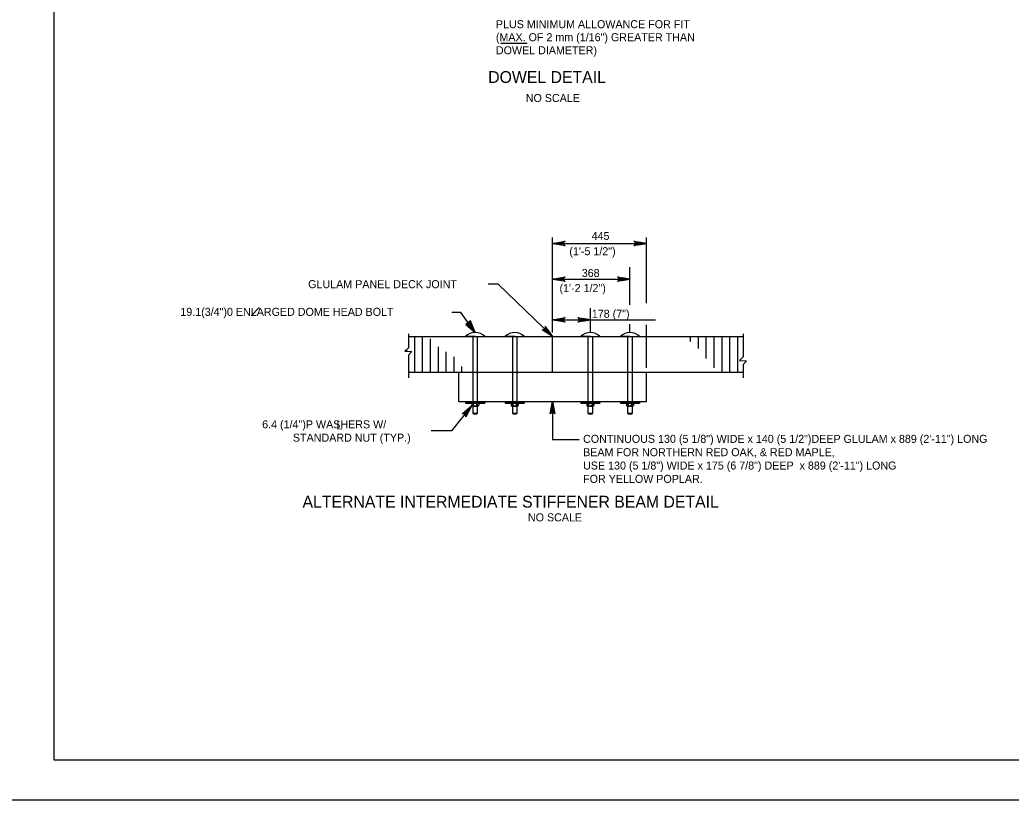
# Model space of a CAD drawing. Extents: x 638263 to 640360, y 293683 to 298655.
# Drawn here: x 639303.6 to 639675, y 294277.5 to 294570 of the extents above; entities that cross this region are included whole.
import ezdxf

# ---------------------------------------------------------------- set-up
doc = ezdxf.new("R2010")
doc.units = 0
for name, color, linetype in [('2', 7, 'Continuous'), ('3', 7, 'Continuous'), ('5', 7, 'Continuous'), ('PLT-BNDY', 7, 'Continuous')]:
    doc.layers.add(name, color=color, linetype=linetype)

msp = doc.modelspace()

# ---------------------------------------------------------------- linework, layer by layer
at = {"layer": '2'}
for p, q in [((639316.46, 294292.46), (639316.46, 294856.46)), ((639449.25, 294452.3), (639449.25, 294447.04)), ((639449.25, 294451.21), (639574.61, 294451.21)), ((639474.18, 294451.21), (639470.61, 294451.21)), ((639473.39, 294422.39), (639473.39, 294451.21)), ((639474.18, 294451.21), (639477.75, 294451.21)), ((639474.97, 294451.21), (639474.97, 294422.39)), ((639488.23, 294422.39), (639488.23, 294451.21)), ((639489.8, 294451.21), (639489.8, 294422.39)), ((639503.18, 294437.92), (639503.18, 294451.21)), ((639516.56, 294422.39), (639516.56, 294451.21)), ((639518.13, 294451.21), (639518.13, 294422.39)), ((639531.39, 294422.39), (639531.39, 294451.21)), ((639532.97, 294451.21), (639532.97, 294422.39)), ((639574.61, 294452.3), (639574.61, 294443.59)), ((639449.25, 294447.04), (639447.87, 294445.74)), ((639447.87, 294445.74), (639450.47, 294445.59)), ((639450.47, 294445.59), (639449.25, 294444.23)), ((639449.25, 294444.23), (639449.25, 294435.71)), ((639574.61, 294443.59), (639573.23, 294442.29)), ((639573.23, 294442.29), (639575.83, 294442.15)), ((639575.83, 294442.15), (639574.61, 294440.78)), ((639574.61, 294440.78), (639574.61, 294435.71)), ((639449.25, 294437.92), (639574.61, 294437.92)), ((639468.04, 294426.9), (639468.04, 294437.92)), ((639538.32, 294426.9), (639538.32, 294437.92)), ((639468.04, 294426.9), (639538.32, 294426.9)), ((639475.49, 294426.3), (639472.88, 294426.3)), ((639472.88, 294426.3), (639472.88, 294425.41)), ((639472.88, 294425.41), (639473.25, 294425.2)), ((639473.25, 294425.2), (639475.11, 294425.2)), ((639473.57, 294425.2), (639473.57, 294426.3)), ((639474.8, 294425.2), (639474.8, 294426.3)), ((639475.11, 294425.2), (639475.49, 294425.41)), ((639475.49, 294426.3), (639475.49, 294425.41)), ((639487.71, 294426.3), (639487.71, 294425.41)), ((639490.32, 294426.3), (639487.71, 294426.3)), ((639487.71, 294425.41), (639488.09, 294425.2)), ((639488.09, 294425.2), (639489.94, 294425.2)), ((639488.4, 294425.2), (639488.4, 294426.3)), ((639489.63, 294425.2), (639489.63, 294426.3)), ((639489.94, 294425.2), (639490.32, 294425.41)), ((639490.32, 294426.3), (639490.32, 294425.41)), ((639516.04, 294426.3), (639516.04, 294425.41)), ((639518.65, 294426.3), (639516.04, 294426.3)), ((639516.04, 294425.41), (639516.42, 294425.2)), ((639516.42, 294425.2), (639518.27, 294425.2)), ((639516.73, 294425.2), (639516.73, 294426.3)), ((639517.96, 294425.2), (639517.96, 294426.3)), ((639518.27, 294425.2), (639518.65, 294425.41)), ((639518.65, 294426.3), (639518.65, 294425.41)), ((639530.88, 294426.3), (639530.88, 294425.41)), ((639533.49, 294426.3), (639530.88, 294426.3)), ((639530.88, 294425.41), (639531.25, 294425.2)), ((639531.25, 294425.2), (639533.11, 294425.2)), ((639531.57, 294425.2), (639531.57, 294426.3)), ((639532.8, 294425.2), (639532.8, 294426.3)), ((639533.11, 294425.2), (639533.49, 294425.41)), ((639533.49, 294426.3), (639533.49, 294425.41)), ((639474.97, 294422.39), (639473.39, 294422.39)), ((639473.59, 294422.2), (639473.39, 294422.39)), ((639474.77, 294422.2), (639473.59, 294422.2)), ((639474.97, 294422.39), (639474.77, 294422.2)), ((639488.43, 294422.2), (639488.23, 294422.39)), ((639489.8, 294422.39), (639488.23, 294422.39)), ((639489.61, 294422.2), (639488.43, 294422.2)), ((639489.8, 294422.39), (639489.61, 294422.2)), ((639516.76, 294422.2), (639516.56, 294422.39)), ((639518.13, 294422.39), (639516.56, 294422.39)), ((639517.94, 294422.2), (639516.76, 294422.2)), ((639518.13, 294422.39), (639517.94, 294422.2)), ((639531.59, 294422.2), (639531.39, 294422.39)), ((639532.97, 294422.39), (639531.39, 294422.39)), ((639532.77, 294422.2), (639531.59, 294422.2)), ((639532.97, 294422.39), (639532.77, 294422.2)), ((640102.46, 294292.46), (639316.46, 294292.46))]:
    msp.add_line(p, q, dxfattribs=at)
msp.add_lwpolyline([(639474.18, 294452.8), (639468.76, 294460.32), (639465.41, 294460.32)], dxfattribs=at)
msp.add_lwpolyline([(639474.18, 294452.8), (639472.46, 294457.11), (639470.64, 294455.79)], close=True, dxfattribs=at)
for centre, radius, start, end in [((639474.18, 294448.01), 4.79, 41.8701, 138.1299), ((639473.53, 294426.28), 1.08, 233, 307), ((639474.83, 294426.28), 1.08, 233, 307), ((639488.36, 294426.28), 1.08, 233, 307), ((639489.67, 294426.28), 1.08, 233, 307), ((639516.69, 294426.28), 1.08, 233, 307), ((639518, 294426.28), 1.08, 233, 307), ((639531.53, 294426.28), 1.08, 233, 307), ((639532.83, 294426.28), 1.08, 233, 307)]:
    msp.add_arc(centre, radius, start, end, dxfattribs=at)
at = {"layer": '3'}
for p, q in [((639483.8, 294561.24), (639493.68, 294561.24)), ((639390.24, 294459.04), (639393.3, 294462.1)), ((639465.34, 294415.85), (639457.7, 294415.85)), ((639503.18, 294412.69), (639513.16, 294412.69))]:
    msp.add_line(p, q, dxfattribs=at)
for points in [[(639503.18, 294451.21), (639482.84, 294470.88), (639479.05, 294470.88)], [(639474.18, 294452.8), (639470.75, 294456.07), (639471.16, 294455.92), (639471.52, 294455.96), (639471.81, 294456.1), (639472.03, 294456.32), (639472.17, 294456.65), (639472.16, 294457.09), (639474.18, 294452.8), (639472.17, 294456.65), (639472.03, 294456.32), (639474.18, 294452.8), (639471.81, 294456.1), (639471.52, 294455.96), (639474.18, 294452.8), (639471.16, 294455.92)], [(639503.18, 294451.21), (639499.22, 294453.82), (639499.65, 294453.75), (639500.01, 294453.84), (639500.26, 294454.03), (639500.44, 294454.29), (639500.53, 294454.65), (639500.44, 294455.07), (639503.18, 294451.21), (639500.53, 294454.65), (639500.44, 294454.29), (639503.18, 294451.21), (639500.26, 294454.03), (639500.01, 294453.84), (639503.18, 294451.21), (639499.65, 294453.75)], [(639472.88, 294425.41), (639465.34, 294415.85)], [(639472.88, 294425.41), (639470.68, 294421.21), (639470.71, 294421.65), (639470.58, 294421.99), (639470.36, 294422.22), (639470.08, 294422.37), (639469.72, 294422.42), (639469.31, 294422.3), (639472.88, 294425.41), (639469.72, 294422.42), (639470.08, 294422.37), (639472.88, 294425.41), (639470.36, 294422.22), (639470.58, 294421.99), (639472.88, 294425.41), (639470.71, 294421.65)], [(639503.18, 294426.9), (639504.05, 294422.23), (639503.81, 294422.59), (639503.49, 294422.78), (639503.18, 294422.83), (639502.87, 294422.78), (639502.56, 294422.59), (639502.31, 294422.23), (639503.18, 294426.9), (639502.56, 294422.59), (639502.87, 294422.78), (639503.18, 294426.9), (639503.18, 294422.83), (639503.49, 294422.78), (639503.18, 294426.9), (639503.81, 294422.59)], [(639503.18, 294426.9), (639503.18, 294412.69)]]:
    msp.add_lwpolyline(points, dxfattribs=at)
for points in [[(639503.18, 294451.21), (639503.12, 294451.31), (639503.08, 294451.27)], [(639472.88, 294425.41), (639472.78, 294425.34), (639472.83, 294425.3)], [(639503.18, 294426.9), (639503.15, 294426.78), (639503.21, 294426.78)]]:
    msp.add_lwpolyline(points, close=True, dxfattribs=at)
at = {"layer": '5'}
for p, q in [((639503.18, 294452.74), (639503.18, 294488.38)), ((639538.32, 294463.7), (639538.32, 294488.38)), ((639538.32, 294472.69), (639538.32, 294488.38)), ((639503.18, 294486.16), (639538.32, 294486.16)), ((639538.32, 294486.16), (639538.32, 294486.16)), ((639503.18, 294452.74), (639503.18, 294477.21)), ((639532.18, 294471.65), (639532.18, 294477.21)), ((639532.18, 294463.09), (639532.18, 294474.55)), ((639503.18, 294472.78), (639532.18, 294472.78)), ((639532.18, 294472.78), (639532.18, 294472.78)), ((639503.18, 294452.74), (639503.18, 294461.89)), ((639517.35, 294452.74), (639517.35, 294461.89)), ((639503.18, 294457.46), (639541.78, 294457.46)), ((639517.35, 294457.46), (639517.35, 294457.46)), ((639532.18, 294452.74), (639532.18, 294455.91)), ((639538.32, 294439.46), (639538.32, 294455.68)), ((639451.53, 294437.92), (639451.53, 294451.21)), ((639454.48, 294437.92), (639454.48, 294451.21)), ((639489.02, 294451.21), (639485.45, 294451.21)), ((639489.02, 294451.21), (639492.58, 294451.21)), ((639503.18, 294451.21), (639503.18, 294451.21)), ((639517.35, 294451.21), (639513.78, 294451.21)), ((639517.35, 294451.21), (639520.91, 294451.21)), ((639517.35, 294451.21), (639517.35, 294451.21)), ((639532.18, 294451.21), (639528.61, 294451.21)), ((639532.18, 294451.21), (639535.75, 294451.21)), ((639532.18, 294451.21), (639532.18, 294451.21)), ((639554.87, 294449.33), (639554.87, 294451.21)), ((639557.83, 294446.8), (639557.83, 294451.21)), ((639560.78, 294442.97), (639560.78, 294451.21)), ((639563.73, 294439.56), (639563.73, 294451.21)), ((639566.68, 294437.98), (639566.68, 294451.21)), ((639569.64, 294437.92), (639569.64, 294451.21)), ((639572.59, 294437.92), (639572.59, 294451.21)), ((639457.43, 294437.92), (639457.43, 294450.35)), ((639460.39, 294437.92), (639460.39, 294447.35)), ((639448.58, 294445.7), (639448.58, 294446.4)), ((639463.34, 294437.93), (639463.34, 294445.56)), ((639466.29, 294437.93), (639466.29, 294443.62)), ((639469.24, 294437.93), (639469.24, 294439.97)), ((639575.54, 294441.83), (639575.54, 294442.16)), ((639472.2, 294437.93), (639472.2, 294438.05)), ((639538.32, 294437.92), (639538.32, 294437.92)), ((639470.61, 294426.9), (639470.61, 294426.3)), ((639470.61, 294426.6), (639477.75, 294426.6)), ((639470.61, 294426.3), (639477.75, 294426.3)), ((639477.75, 294426.9), (639477.75, 294426.3)), ((639485.45, 294426.9), (639485.45, 294426.3)), ((639485.45, 294426.6), (639492.58, 294426.6)), ((639485.45, 294426.3), (639492.58, 294426.3)), ((639492.58, 294426.9), (639492.58, 294426.3)), ((639513.78, 294426.9), (639513.78, 294426.3)), ((639513.78, 294426.6), (639520.91, 294426.6)), ((639513.78, 294426.3), (639520.91, 294426.3)), ((639520.91, 294426.9), (639520.91, 294426.3)), ((639528.61, 294426.9), (639528.61, 294426.3)), ((639528.61, 294426.6), (639535.75, 294426.6)), ((639528.61, 294426.3), (639535.75, 294426.3)), ((639535.75, 294426.9), (639535.75, 294426.3))]:
    msp.add_line(p, q, dxfattribs=at)
for points in [[(639503.18, 294486.16), (639507.84, 294487.04), (639507.48, 294486.79), (639507.3, 294486.47), (639507.24, 294486.16), (639507.3, 294485.85), (639507.48, 294485.54), (639507.84, 294485.29), (639503.18, 294486.16), (639507.48, 294485.54), (639507.3, 294485.85), (639503.18, 294486.16), (639507.24, 294486.16), (639507.3, 294486.47), (639503.18, 294486.16), (639507.48, 294486.79)], [(639538.32, 294486.16), (639533.66, 294485.29), (639534.02, 294485.54), (639534.2, 294485.85), (639534.26, 294486.16), (639534.2, 294486.47), (639534.02, 294486.79), (639533.66, 294487.04), (639538.32, 294486.16), (639534.02, 294486.79), (639534.2, 294486.47), (639538.32, 294486.16), (639534.26, 294486.16), (639534.2, 294485.85), (639538.32, 294486.16), (639534.02, 294485.54)], [(639503.18, 294472.78), (639507.84, 294473.66), (639507.48, 294473.41), (639507.3, 294473.1), (639507.24, 294472.78), (639507.3, 294472.47), (639507.48, 294472.16), (639507.84, 294471.91), (639503.18, 294472.78), (639507.48, 294472.16), (639507.3, 294472.47), (639503.18, 294472.78), (639507.24, 294472.78), (639507.3, 294473.1), (639503.18, 294472.78), (639507.48, 294473.41)], [(639532.18, 294472.78), (639527.52, 294471.91), (639527.88, 294472.16), (639528.06, 294472.47), (639528.12, 294472.78), (639528.06, 294473.1), (639527.88, 294473.41), (639527.52, 294473.66), (639532.18, 294472.78), (639527.88, 294473.41), (639528.06, 294473.1), (639532.18, 294472.78), (639528.12, 294472.78), (639528.06, 294472.47), (639532.18, 294472.78), (639527.88, 294472.16)], [(639503.18, 294457.46), (639507.84, 294458.34), (639507.48, 294458.09), (639507.3, 294457.78), (639507.24, 294457.46), (639507.3, 294457.15), (639507.48, 294456.84), (639507.84, 294456.59), (639503.18, 294457.46), (639507.48, 294456.84), (639507.3, 294457.15), (639503.18, 294457.46), (639507.24, 294457.46), (639507.3, 294457.78), (639503.18, 294457.46), (639507.48, 294458.09)], [(639517.35, 294457.46), (639512.69, 294456.59), (639513.05, 294456.84), (639513.23, 294457.15), (639513.29, 294457.46), (639513.23, 294457.78), (639513.05, 294458.09), (639512.69, 294458.34), (639517.35, 294457.46), (639513.05, 294458.09), (639513.23, 294457.78), (639517.35, 294457.46), (639513.29, 294457.46), (639513.23, 294457.15), (639517.35, 294457.46), (639513.05, 294456.84)]]:
    msp.add_lwpolyline(points, dxfattribs=at)
for points in [[(639506.14, 294486.65), (639506.14, 294485.67), (639503.18, 294486.16)], [(639535.37, 294486.65), (639535.37, 294485.67), (639538.32, 294486.16)], [(639506.14, 294473.28), (639506.14, 294472.29), (639503.18, 294472.78)], [(639529.23, 294473.28), (639529.23, 294472.29), (639532.18, 294472.78)], [(639506.14, 294457.96), (639506.14, 294456.97), (639503.18, 294457.46)], [(639514.39, 294457.96), (639514.39, 294456.97), (639517.35, 294457.46)]]:
    msp.add_lwpolyline(points, close=True, dxfattribs=at)
for centre in [(639489.02, 294448.01), (639517.35, 294448.01), (639532.18, 294448.01)]:
    msp.add_arc(centre, 4.79, 41.8701, 138.1299, dxfattribs=at)
at = {"layer": 'PLT-BNDY'}
msp.add_lwpolyline([(639276.46, 294871.46), (640117.46, 294871.46), (640117.46, 294277.46), (639276.46, 294277.46)], close=True, dxfattribs=at)

# ---------------------------------------------------------------- texts
at = {"layer": '3'}
for s, height, p in [('PLUS MINIMUM ALLOWANCE FOR FIT', 3, (639481.94, 294566.84)), ('(MAX. OF 2 mm (1/16") GREATER THAN', 3, (639481.94, 294561.95)), ('DOWEL DIAMETER)', 3, (639481.94, 294557.05)), ('DOWEL DETAIL', 4.4292, (639479.06, 294546.31)), ('NO SCALE', 3, (639493.15, 294539.17)), ('GLULAM PANEL DECK JOINT', 3, (639411.61, 294469.38)), ('19.1(3/4")0 ENLARGED DOME HEAD BOLT', 3, (639363.71, 294459.01)), ('6.4 (1/4")P WASHERS W/ ', 3, (639394.38, 294416.85)), ('L', 3, (639422.18, 294416.42)), ('STANDARD NUT (TYP.)', 3, (639405.89, 294411.85)), ('CONTINUOUS 130 (5 1/8") WIDE x 140 (5 1/2")DEEP GLULAM x 889 (2\'-11") LONG', 3, (639514.62, 294411.4)), ('BEAM FOR NORTHERN RED OAK, & RED MAPLE,', 3, (639514.62, 294406.4)), ('USE 130 (5 1/8") WIDE x 175 (6 7/8") DEEP  x 889 (2\'-11") LONG', 3, (639514.62, 294401.4)), ('FOR YELLOW POPLAR.', 3, (639514.62, 294396.4)), ('ALTERNATE INTERMEDIATE STIFFENER BEAM DETAIL', 4.4292, (639409.49, 294387.12)), ('NO SCALE', 3, (639493.95, 294381.96))]:
    msp.add_text(s, height=height, dxfattribs=at).set_placement(p)
at = {"layer": '5'}
for s, p in [('445', (639517.8, 294487.45)), ('(1\'-5 1/2")', (639509.46, 294481.75)), ('368', (639514.11, 294473.58)), ('(1\'-2 1/2")', (639505.78, 294467.93)), ('178 (7")', (639517.89, 294458.3))]:
    msp.add_text(s, height=3, dxfattribs=at).set_placement(p)

doc.saveas('drawing.dxf')
